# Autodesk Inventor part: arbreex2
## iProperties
Created: 2006-05
Part Number: arbreex2
Document SubType Name: Modeling
Designer: Administrateur
Manufacturer: Standard
Standards Organization: Custom
Author: Administrateur
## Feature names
1. Révolution1 [Revolution]
2. Chanfrein1 [Chamfer]
3. Extrusion1
4. Miroir1 [Mirror]
